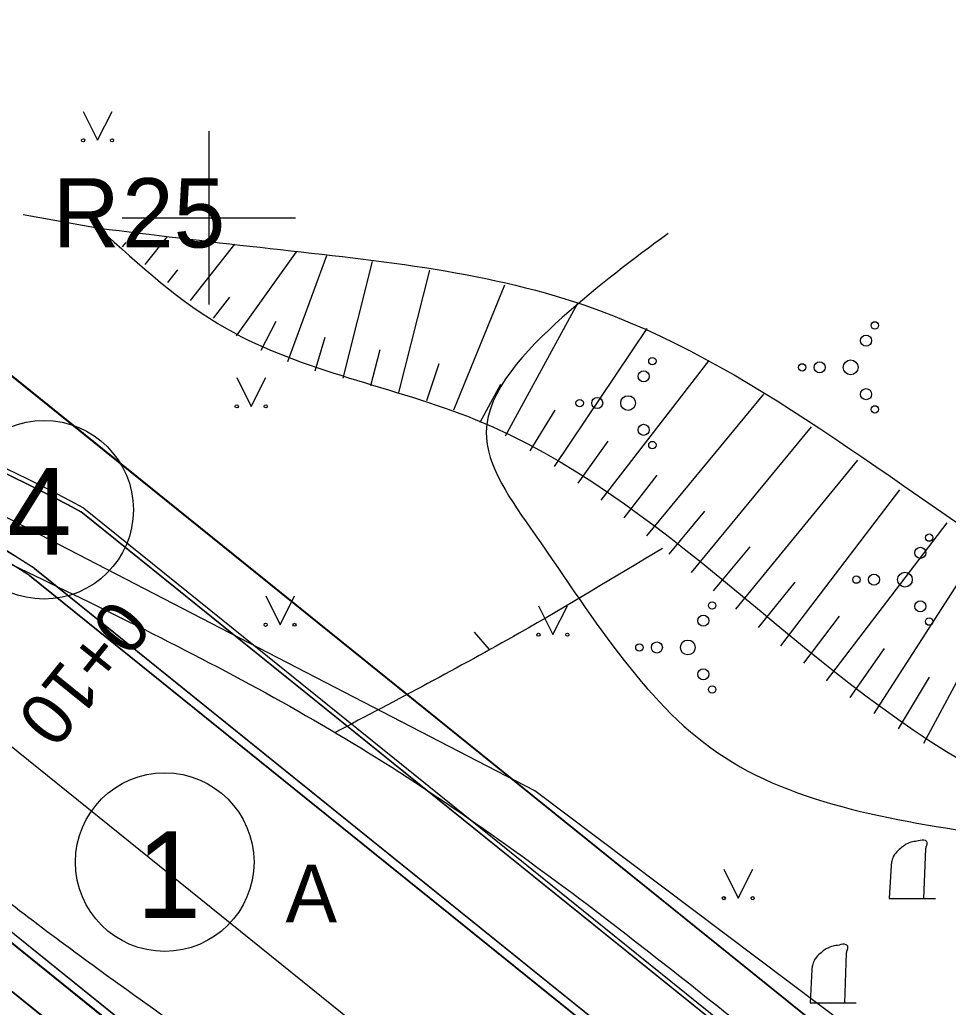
# Model space of a CAD drawing. Extents: x 514086 to 514457, y 297399 to 297567.
# Drawn here: x 514146.73 to 514162.8, y 297486.33 to 297503.43 of the extents above; entities that cross this region are included whole.
import ezdxf

# ---------------------------------------------------------------- set-up
doc = ezdxf.new("R2010")
doc.units = 0
for name, color, linetype in [('AA_Apzimejumi', 7, 'Continuous'), ('AA_Brauktuve', 7, 'Continuous'), ('AA_cela_mala', 7, 'Continuous'), ('AA_Ielas_ass', 7, 'Continuous'), ('AA_Ietve', 7, 'Continuous'), ('AA_izmeri', 7, 'Continuous'), ('AA_Nomale', 7, 'Continuous'), ('AA_Zale', 7, 'Continuous'), ('Level 21', 7, 'Continuous'), ('Level 23', 7, 'Continuous'), ('Level 29', 7, 'Continuous'), ('Level 30', 7, 'Continuous'), ('Level 31', 7, 'Continuous'), ('Level 32', 7, 'Continuous'), ('Level 37', 7, 'Continuous'), ('Level 41', 7, 'Continuous'), ('Level 46', 7, 'Continuous'), ('Level 8', 7, 'Continuous')]:
    doc.layers.add(name, color=color, linetype=linetype)

msp = doc.modelspace()

# ---------------------------------------------------------------- linework, layer by layer
at = {"layer": 'AA_Apzimejumi'}
for centre in [(514147.147, 297494.944), (514149.236, 297488.843)]:
    msp.add_circle(centre, 1.546, dxfattribs=at)
at = {"layer": 'AA_Brauktuve'}
for points in [[(514184.371, 297463.607), (514146.894, 297493.805)], [(514139.852, 297493.058), (514181.234, 297459.714)]]:
    msp.add_lwpolyline(points, dxfattribs=at)
msp.add_arc((514131.177, 297469.417), 29.014, 57.1989, 75.8142, dxfattribs=at)
at = {"layer": 'AA_cela_mala'}
for p, q in [((514185.262, 297464.713), (514147.785, 297494.911)), ((514147.835, 297494.973), (514185.313, 297464.775)), ((514146.988, 297493.922), (514146.976, 297493.931)), ((514184.466, 297463.724), (514146.988, 297493.922)), ((514146.894, 297493.805), (514184.371, 297463.607)), ((514139.852, 297493.058), (514181.234, 297459.714)), ((514139.758, 297492.942), (514181.14, 297459.597))]:
    msp.add_line(p, q, dxfattribs=at)
for centre, radius, start, end in [((514131.177, 297469.417), 29.164, 57.1989, 75.7708), ((514135.157, 297471.651), 26.465, 61.4692, 79.8096), ((514135.157, 297471.651), 26.545, 61.4692, 79.8096), ((514131.177, 297469.417), 29.014, 57.1989, 75.8142)]:
    msp.add_arc(centre, radius, start, end, dxfattribs=at)
at = {"layer": 'AA_Ielas_ass'}
msp.add_line((514145.326, 297491.858), (514156.673, 297482.715), dxfattribs=at)
at = {"layer": 'AA_Ietve'}
for points in [[(514185.262, 297464.713), (514147.791, 297494.906)], [(514146.982, 297493.927), (514184.466, 297463.724)]]:
    msp.add_lwpolyline(points, dxfattribs=at)
for centre, radius, start, end in [((514135.157, 297471.651), 26.465, 61.4848, 79.8096), ((514131.177, 297469.417), 29.164, 57.1832, 72.6628)]:
    msp.add_arc(centre, radius, start, end, dxfattribs=at)
at = {"layer": 'AA_Nomale'}
for points in [[(514181.14, 297459.597), (514139.77, 297492.933)], [(514139.413, 297492.389), (514139.411, 297492.386), (514180.732, 297459.091)]]:
    msp.add_lwpolyline(points, dxfattribs=at)
at = {"layer": 'AA_Zale'}
for p, q in [((514146.591, 297497.26), (514175.859, 297473.677)), ((514139.35, 297492.435), (514180.732, 297459.091))]:
    msp.add_line(p, q, dxfattribs=at)
for points in [[(514197.26, 297461.293), (514196.873, 297461.611), (514193.845, 297459.804), (514175.859, 297473.677), (514146.591, 297497.26)], [(514147.835, 297494.973), (514185.313, 297464.775)], [(514180.732, 297459.091), (514139.411, 297492.386), (514139.381, 297492.411)]]:
    msp.add_lwpolyline(points, dxfattribs=at)
msp.add_arc((514135.157, 297471.651), 26.545, 61.4692, 79.8096, dxfattribs=at)
at = {"layer": 'Level 21'}
msp.add_spline([(514157.951, 297499.728), (514156.119, 297498.271), (514154.804, 297496.296), (514155.649, 297494.512), (514158.938, 297490.653), (514163.925, 297489.256), (514171.388, 297488.349), (514175.429, 297488.349)], degree=3, dxfattribs=at)
at = {"layer": 'Level 23'}
for p, q in [((514147.823, 297501.843), (514148.073, 297501.343)), ((514148.073, 297501.343), (514148.323, 297501.843)), ((514150.484, 297497.235), (514150.734, 297496.735)), ((514150.734, 297496.735), (514150.984, 297497.235)), ((514150.984, 297493.454), (514151.234, 297492.954)), ((514151.234, 297492.954), (514151.484, 297493.454)), ((514155.708, 297493.282), (514155.958, 297492.782)), ((514155.958, 297492.782), (514156.208, 297493.282)), ((514158.917, 297488.719), (514159.167, 297488.219)), ((514159.167, 297488.219), (514159.417, 297488.719))]:
    msp.add_line(p, q, dxfattribs=at)
for centre, radius in [((514147.823, 297501.342), 0.028), ((514148.323, 297501.342), 0.0263), ((514161.533, 297498.137), 0.064), ((514161.381, 297497.874), 0.096), ((514157.68, 297497.519), 0.064), ((514160.273, 297497.41), 0.064), ((514160.577, 297497.41), 0.096), ((514161.113, 297497.41), 0.128), ((514157.528, 297497.256), 0.096), ((514161.381, 297496.946), 0.096), ((514156.421, 297496.792), 0.064), ((514156.725, 297496.792), 0.096), ((514157.26, 297496.792), 0.128), ((514150.484, 297496.735), 0.028), ((514150.984, 297496.735), 0.0263), ((514161.533, 297496.683), 0.064), ((514157.528, 297496.328), 0.096), ((514157.68, 297496.065), 0.064), ((514162.472, 297494.462), 0.064), ((514162.32, 297494.199), 0.096), ((514161.213, 297493.735), 0.064), ((514161.517, 297493.735), 0.096), ((514162.053, 297493.735), 0.128), ((514162.32, 297493.271), 0.096), ((514158.714, 297493.287), 0.064), ((514158.562, 297493.024), 0.096), ((514162.472, 297493.008), 0.064), ((514150.983, 297492.953), 0.028), ((514151.483, 297492.953), 0.0263), ((514155.708, 297492.781), 0.028), ((514156.208, 297492.781), 0.0263), ((514158.294, 297492.56), 0.128), ((514157.455, 297492.56), 0.064), ((514157.758, 297492.56), 0.096), ((514158.562, 297492.096), 0.096), ((514158.714, 297491.833), 0.064), ((514158.917, 297488.219), 0.028), ((514159.417, 297488.219), 0.0263)]:
    msp.add_circle(centre, radius, dxfattribs=at)
at = {"layer": 'Level 29'}
msp.add_line((514139.316, 297503.122), (514175.859, 297473.677), dxfattribs=at)
at = {"layer": 'Level 30'}
for p, q in [((514150, 297501.5), (514150, 297500)), ((514148.5, 297500), (514150, 297500)), ((514150, 297500), (514150, 297498.5)), ((514150, 297500), (514151.5, 297500))]:
    msp.add_line(p, q, dxfattribs=at)
at = {"layer": 'Level 31'}
for p, q in [((514148.114, 297499.808), (514148.122, 297499.818)), ((514148.507, 297499.499), (514148.566, 297499.574)), ((514148.9, 297499.19), (514149.286, 297499.679)), ((514149.685, 297498.571), (514150.45, 297499.541)), ((514150.476, 297497.959), (514151.518, 297499.412)), ((514151.366, 297497.51), (514152.041, 297499.348)), ((514152.323, 297497.221), (514152.833, 297499.242)), ((514149.292, 297498.88), (514149.465, 297499.099)), ((514153.292, 297496.977), (514153.826, 297499.091)), ((514154.244, 297496.673), (514155.125, 297498.84)), ((514150.078, 297498.261), (514150.364, 297498.624)), ((514155.137, 297496.223), (514156.388, 297498.522)), ((514150.907, 297497.706), (514151.163, 297498.209)), ((514155.983, 297495.692), (514157.588, 297498.083)), ((514151.84, 297497.351), (514152.016, 297497.935)), ((514152.807, 297497.099), (514152.965, 297497.721)), ((514153.772, 297496.838), (514153.987, 297497.479)), ((514156.796, 297495.109), (514158.666, 297497.531)), ((514154.697, 297496.462), (514155.056, 297497.121)), ((514157.583, 297494.493), (514159.608, 297496.949)), ((514155.564, 297495.965), (514155.997, 297496.671)), ((514158.355, 297493.857), (514160.434, 297496.38)), ((514156.394, 297495.406), (514156.915, 297496.131)), ((514159.128, 297493.222), (514161.238, 297495.805)), ((514157.191, 297494.803), (514157.763, 297495.544)), ((514159.902, 297492.59), (514161.964, 297495.287)), ((514157.969, 297494.175), (514158.586, 297494.923)), ((514160.697, 297491.983), (514162.786, 297494.716)), ((514158.741, 297493.539), (514159.371, 297494.304)), ((514161.521, 297491.416), (514163.395, 297494.328)), ((514162.378, 297490.903), (514164.024, 297493.957)), ((514159.515, 297492.906), (514160.154, 297493.688)), ((514160.3, 297492.286), (514160.922, 297493.1)), ((514161.106, 297491.695), (514161.701, 297492.543)), ((514161.944, 297491.15), (514162.476, 297492.045))]:
    msp.add_line(p, q, dxfattribs=at)
for points in [[(514148.099, 297499.821), (514150.307, 297498.081), (514154.61, 297496.51), (514163.344, 297490.425), (514171.508, 297488.45), (514174.972, 297488.45)], [(514148.099, 297499.821), (514150.886, 297499.489), (514156.496, 297498.491), (514164.495, 297493.708), (514170.885, 297490.886), (514174.455, 297490.181)]]:
    msp.add_spline(points, degree=3, dxfattribs=at)
at = {"layer": 'Level 32'}
for p, q in [((514146.786, 297500.059), (514148.099, 297499.821)), ((514154.862, 297492.523), (514154.602, 297492.826))]:
    msp.add_line(p, q, dxfattribs=at)
msp.add_spline([(514157.855, 297494.275), (514155.371, 297492.806), (514152.187, 297491.088)], degree=3, dxfattribs=at)
at = {"layer": 'Level 37'}
for points in [[(514139.874, 297497.035), (514148.452, 297493.087), (514152.9, 297490.654), (514155.012, 297489.24), (514157.055, 297487.727), (514160.163, 297485.252), (514163.225, 297482.729), (514166.288, 297480.21), (514169.399, 297477.75), (514184.679, 297466.049), (514188.685, 297462.979), (514190.692, 297461.445), (514192.708, 297459.912), (514193.134, 297459.688), (514193.613, 297459.574), (514194.114, 297459.524), (514194.606, 297459.489), (514195.045, 297459.442), (514195.506, 297459.417), (514195.979, 297459.548), (514196.259, 297459.707)], [(514136.849, 297494.086), (514140.775, 297492.444), (514142.699, 297491.153), (514143.967, 297490.173), (514145.225, 297489.179), (514146.485, 297488.19), (514147.764, 297487.226), (514149.635, 297485.885), (514151.52, 297484.563), (514153.402, 297483.236), (514155.263, 297481.88), (514159.161, 297478.934), (514163.043, 297475.965), (514166.923, 297472.996), (514170.82, 297470.048), (514173.26, 297468.237), (514175.709, 297466.438), (514178.159, 297464.639), (514180.6, 297462.828), (514184.429, 297459.874), (514186.323, 297458.371), (514188.215, 297456.863), (514189.034, 297456.154), (514191.11, 297453.709)]]:
    msp.add_spline(points, degree=3, dxfattribs=at)
at = {"layer": 'Level 41'}
for p, q in [((514162.383, 297488.213), (514162.417, 297489.078)), ((514161.814, 297488.786), (514161.783, 297488.213)), ((514161.783, 297488.213), (514162.083, 297488.213)), ((514162.083, 297488.213), (514162.383, 297488.213)), ((514162.383, 297488.213), (514162.583, 297488.213)), ((514161.01, 297486.408), (514161.044, 297487.273)), ((514160.441, 297486.981), (514160.41, 297486.408)), ((514160.41, 297486.408), (514160.71, 297486.408)), ((514160.71, 297486.408), (514161.01, 297486.408)), ((514161.01, 297486.408), (514161.21, 297486.408))]:
    msp.add_line(p, q, dxfattribs=at)
for points in [[(514162.417, 297489.078), (514162.421, 297489.109), (514162.424, 297489.12), (514162.439, 297489.182), (514162.409, 297489.217), (514162.287, 297489.211), (514162.183, 297489.193), (514162.077, 297489.154), (514162.012, 297489.11), (514161.937, 297489.046), (514161.857, 297488.948), (514161.826, 297488.859), (514161.814, 297488.785)], [(514161.044, 297487.273), (514161.048, 297487.304), (514161.051, 297487.315), (514161.066, 297487.377), (514161.036, 297487.412), (514160.914, 297487.406), (514160.81, 297487.388), (514160.704, 297487.349), (514160.639, 297487.305), (514160.564, 297487.241), (514160.484, 297487.143), (514160.453, 297487.054), (514160.441, 297486.98)]]:
    msp.add_spline(points, degree=3, dxfattribs=at)
at = {"layer": 'Level 46'}
msp.add_lwpolyline([(514139.134, 297486.37), (514229.261, 297420.493), (514237.863, 297414.208), (514250.009, 297428.181), (514295.433, 297494.723), (514312.775, 297524.542), (514316.491, 297528.738), (514320.446, 297531.016), (514328.236, 297532.215), (514332.539, 297530.572), (514332.631, 297530.536), (514341.642, 297542.18), (514320.211, 297553.997), (514285.885, 297496.27), (514243.195, 297433.696), (514241.534, 297432.407), (514239.451, 297432.203), (514209.969, 297445.237), (514194.45, 297457.413), (514175.859, 297473.677), (514139.316, 297503.122), (514133.046, 297508.174), (514130.604, 297489.221)], close=True, dxfattribs=at)
at = {"layer": 'Level 8'}
msp.add_lwpolyline([(514200.623, 297456.189), (514178.139, 297473.151), (514155.647, 297490.079), (514143.111, 297496.557), (514135.656, 297500), (514119.377, 297505.512), (514108.036, 297513.213), (514096.037, 297522.278)], dxfattribs=at)

# ---------------------------------------------------------------- texts
at = {"layer": 'AA_Apzimejumi'}
for s, p in [('4', (514146.508, 297494.168)), ('1', (514148.75, 297487.874))]:
    msp.add_text(s, height=1.5, dxfattribs=at).set_placement(p)
at = {"layer": 'AA_Ielas_ass'}
msp.add_text(' 0+10', height=0.9, rotation=231.1394, dxfattribs=at).set_placement((514148.553, 297493.713))
at = {"layer": 'AA_izmeri'}
for s, p in [('R', (514147.298, 297499.486)), ('25', (514148.498, 297499.486))]:
    msp.add_text(s, height=1.2, dxfattribs=at).set_placement(p)
at = {"layer": 'Level 37'}
msp.add_text('A', height=1, dxfattribs=at).set_placement((514151.328, 297487.801))

doc.saveas('drawing.dxf')
